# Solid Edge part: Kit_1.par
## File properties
Last saved by: bmolnar
Revision: 76
Dokumentum tartalom típus: 0
Sűrűség: 0,000 kg/m^3
Pontosság: 0,990
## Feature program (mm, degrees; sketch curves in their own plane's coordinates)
base feature "unnamed BaseFeature 1"
sketch for "Furat_1" plane through (-20.15, 0, -7.65) normal (1, 0, 0) x-axis (0, -1, 0)
  hole centre (0, -15.15) bore radius 2.067
hole "Furat_1" nominal diameter 5 finite  StartChamferOffset = 0.6 mm; StartChamferAngle = 45 deg
sketch for "Furat_2" plane through (-13, 13, 5.1) normal (0, 0, -1) x-axis (0, -1, 0)
  hole centre (0, 0) bore radius 2.067
hole "Furat_2" nominal diameter 5
sketch for "unnamed Hole 1" plane through (-13, 13, 5.1) normal (0, 0, -1) x-axis (0, -1, 0)
  hole centre (26, 0) bore radius 2.067
hole "unnamed Hole 1"
sketch for "unnamed Hole 2" plane through (-13, 13, 5.1) normal (0, 0, -1) x-axis (0, -1, 0)
  hole centre (26, -26) bore radius 2.067
hole "unnamed Hole 2"
sketch for "unnamed Hole 3" plane through (-13, 13, 5.1) normal (0, 0, -1) x-axis (0, -1, 0)
  hole centre (0, -26) bore radius 2.067
hole "unnamed Hole 3"
pattern "unnamed Pattern 1" of "Furat_2", "unnamed Hole 1", "unnamed Hole 2", "unnamed Hole 3"
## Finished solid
Body 1: solid body, 245 faces, 610 edges, 376 vertices, 3 internal voids.
  Faces by surface: plane 129, cylinder 52, swept 42, cone 16, torus 6
  Edges by curve: line 381, circle 135, spline 88, curve on surface 5, ellipse 1
Bounding box of the edges (mm; curved faces can reach further): 40.300 x 40.300 x 12.500, from (-20.15, -20.15, 0) to (20.15, 20.15, 12.5).
Cylindrical faces by radius (mm): R0.2 x18, R0.4246 x1, R0.4865 x1, R2.067 x5, R3.75 x2, R4 x4, R4.1 x12, R4.5 x1, R5.45 x2, R5.55 x2, R13.75 x4
Conical faces (half-angle, radius in mm at the cone's reference point): 0.5 deg R5 x4, 45 deg R2.317 x2, 45 deg R2.367 x2, 45 deg R2.667 x1, 45 deg R4.25 x2, 45 deg R4.65 x1, 45 deg R5.3 x2, 45 deg R5.35 x2
Toroidal faces (ring radius, tube radius in mm): R3.8 r0.2 x2, R4.4 r0.4 x2, R9.4957 r0.5 x1, R11.0043 r0.5 x1
Planar faces by outward normal: +x 5, +y 13, +z 4, -x 7, -y 16, -z 15, oblique 69
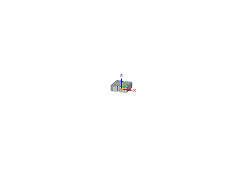
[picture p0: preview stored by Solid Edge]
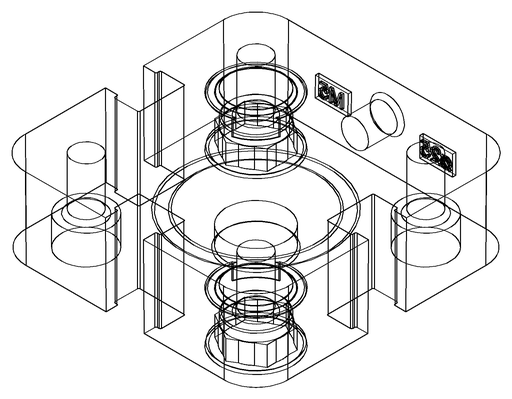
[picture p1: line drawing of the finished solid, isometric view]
